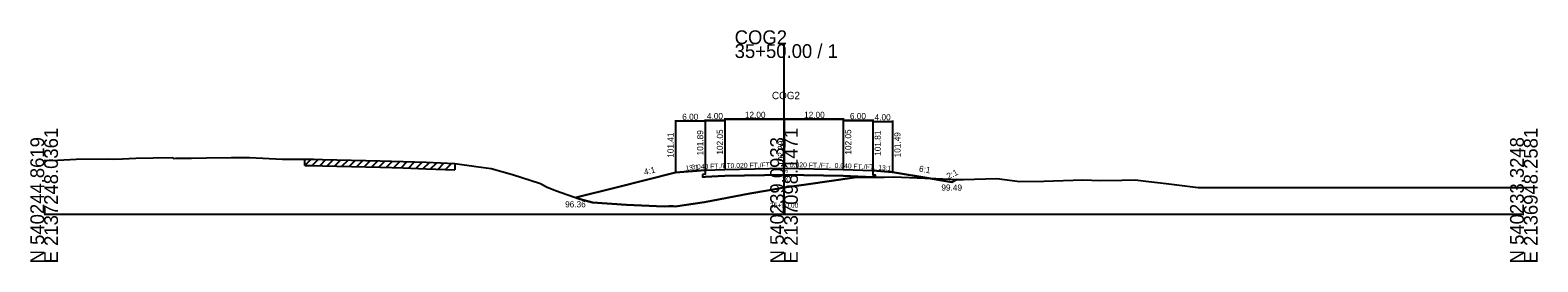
# Model space of a CAD drawing. Extents: x -13397 to 2303, y -10 to 39059.
# Drawn here: x 997.2 to 1302.8, y 10990.3 to 11037.3 of the extents above; entities that cross this region are included whole.
import ezdxf

# ---------------------------------------------------------------- set-up
doc = ezdxf.new("R2010")
doc.units = 0
for name, color, linetype in [('Level 5', 7, 'Continuous'), ('Level 53', 7, 'Continuous'), ('Level 54', 7, 'Continuous'), ('Level 55', 7, 'Continuous'), ('Level 7', 7, 'Continuous'), ('RD_GPK_XS_Cell', 7, 'Continuous'), ('RD_XS_EwShp', 7, 'Continuous'), ('RD_XS_ExGround', 7, 'Continuous'), ('RD_XS_ExPaveRet', 7, 'Continuous'), ('RD_XS_Pave', 7, 'Continuous'), ('RD_XS_TX_Baseline', 7, 'Continuous'), ('RD_XS_TX_Elev_EX', 7, 'Continuous'), ('RD_XS_TX_Elev_PR', 7, 'Continuous'), ('RD_XS_TX_Station', 7, 'Continuous')]:
    doc.layers.add(name, color=color, linetype=linetype)

msp = doc.modelspace()

# ---------------------------------------------------------------- linework, layer by layer
at = {"layer": 'Level 5'}
for p, q in [((1134, 11008.06), (1133.5, 11008.04)), ((1133.5, 11008.04), (1133.5, 11007.54)), ((1134, 11008.89), (1134, 11008.06)), ((1138, 11007.72), (1134, 11007.56)), ((1138, 11007.72), (1134, 11007.56)), ((1138, 11007.72), (1134, 11007.56)), ((1134, 11007.56), (1138, 11007.72)), ((1150, 11007.96), (1138, 11007.72)), ((1150, 11007.96), (1138, 11007.72)), ((1150, 11007.96), (1138, 11007.72)), ((1138, 11007.72), (1150, 11007.96)), ((1138, 11007.72), (1150, 11007.96)), ((1162, 11007.72), (1150, 11007.96)), ((1162, 11007.72), (1150, 11007.96)), ((1150, 11007.96), (1162, 11007.72)), ((1150, 11007.96), (1162, 11007.72)), ((1150, 11007.96), (1162, 11007.72)), ((1168, 11007.48), (1162, 11007.72)), ((1162, 11007.72), (1168, 11007.48)), ((1162, 11007.72), (1168, 11007.48)), ((1162, 11007.72), (1168, 11007.48)), ((1168, 11008.81), (1168, 11007.98)), ((1168, 11007.98), (1168.5, 11007.96)), ((1168.5, 11007.96), (1168.5, 11007.46)), ((1133.5, 11007.54), (1134, 11007.56)), ((1168.5, 11007.46), (1168, 11007.48))]:
    msp.add_line(p, q, dxfattribs=at)
at = {"layer": 'Level 54'}
for p, q in [((1128, 11019.04), (1128, 11008.61)), ((1134, 11018.84), (1128, 11018.84)), ((1134, 11019.2), (1134, 11009.09)), ((1134, 11019.2), (1134, 11009.09)), ((1134, 11019.2), (1134, 11009.09)), ((1134, 11019.2), (1134, 11009.09)), ((1134, 11019.04), (1134, 11009.09)), ((1134, 11019), (1138, 11019)), ((1134, 11019), (1138, 11019)), ((1134, 11019), (1138, 11019)), ((1138, 11019), (1134, 11019)), ((1138, 11019.44), (1138, 11009.25)), ((1138, 11019.44), (1138, 11009.25)), ((1138, 11019.44), (1138, 11009.25)), ((1138, 11019.44), (1138, 11009.25)), ((1138, 11019.44), (1138, 11009.25)), ((1138, 11019.24), (1150, 11019.24)), ((1138, 11019.24), (1150, 11019.24)), ((1138, 11019.24), (1150, 11019.24)), ((1150, 11019.24), (1138, 11019.24)), ((1150, 11019.24), (1138, 11019.24)), ((1138, 11019.2), (1138, 11009.25)), ((1138, 11019.2), (1138, 11009.25)), ((1138, 11019.2), (1138, 11009.25)), ((1138, 11019.2), (1138, 11009.25)), ((1150, 11019.44), (1150, 11009.49)), ((1150, 11019.44), (1150, 11009.49)), ((1150, 11019.44), (1150, 11009.49)), ((1150, 11019.44), (1150, 11009.49)), ((1150, 11019.44), (1150, 11009.49)), ((1150, 11019.44), (1150, 11009.49)), ((1150, 11019.44), (1150, 11009.49)), ((1150, 11019.44), (1150, 11009.49)), ((1150, 11019.44), (1150, 11009.49)), ((1150, 11019.44), (1150, 11009.49)), ((1150, 11019.24), (1162, 11019.24)), ((1150, 11019.24), (1162, 11019.24)), ((1162, 11019.24), (1150, 11019.24)), ((1162, 11019.24), (1150, 11019.24)), ((1162, 11019.24), (1150, 11019.24)), ((1162, 11019.44), (1162, 11009.25)), ((1162, 11019.44), (1162, 11009.25)), ((1162, 11019.44), (1162, 11009.25)), ((1162, 11019.44), (1162, 11009.25)), ((1162, 11019.44), (1162, 11009.25)), ((1162, 11019.2), (1162, 11009.25)), ((1162, 11019.2), (1162, 11009.25)), ((1162, 11019.2), (1162, 11009.25)), ((1162, 11019.2), (1162, 11009.25)), ((1162, 11019), (1168, 11019)), ((1168, 11019), (1162, 11019)), ((1168, 11019), (1162, 11019)), ((1168, 11019), (1162, 11019)), ((1168, 11019.2), (1168, 11009.01)), ((1168, 11019.2), (1168, 11009.01)), ((1168, 11019.2), (1168, 11009.01)), ((1168, 11019.2), (1168, 11009.01)), ((1168, 11018.96), (1168, 11009.01)), ((1168, 11018.76), (1172, 11018.76)), ((1172, 11018.96), (1172, 11008.69))]:
    msp.add_line(p, q, dxfattribs=at)
at = {"layer": 'Level 7'}
for p, q in [((1128, 11008.41), (1116, 11005.41)), ((1134, 11008.89), (1128, 11008.41)), ((1168, 11008.81), (1172, 11008.49)), ((1172, 11008.49), (1184, 11006.49)), ((1116, 11005.41), (1107.78, 11003.36)), ((1184, 11006.49), (1185.06, 11007.02))]:
    msp.add_line(p, q, dxfattribs=at)
at = {"layer": 'RD_GPK_XS_Cell'}
for p, q in [((1150, 11000), (1150, 11034.45)), ((1000, 11000), (1150, 11000)), ((1150, 11000), (1300, 11000))]:
    msp.add_line(p, q, dxfattribs=at)
at = {"layer": 'RD_XS_EwShp'}
for points in [[(1133.5, 11008.04), (1133.5, 11007.54), (1134, 11007.56), (1138, 11007.72), (1150, 11007.96), (1162, 11007.72), (1168, 11007.48), (1168.5, 11007.46), (1164.28, 11007.38), (1154.5, 11006), (1150.06, 11005.36), (1146.68, 11004.81), (1143.08, 11004.16), (1138.46, 11003.29), (1133.9, 11002.39), (1127.96, 11001.5), (1127.53, 11001.6), (1126.64, 11001.58), (1125.71, 11001.5), (1118.09, 11001.87), (1111.16, 11002.31), (1108.69, 11003.04), (1107.78, 11003.36), (1116, 11005.41), (1128, 11008.41), (1134, 11008.89), (1134, 11008.06)], [(1168, 11008.81), (1168, 11007.98), (1168.5, 11007.96), (1168.5, 11007.46), (1170.31, 11007.49), (1172.25, 11007.54), (1178.57, 11007.3), (1179.33, 11007.27), (1172, 11008.49)], [(1179.33, 11007.27), (1185.03, 11007.02), (1185.06, 11007.02), (1184, 11006.49)]]:
    msp.add_lwpolyline(points, close=True, dxfattribs=at)
at = {"layer": 'RD_XS_ExGround'}
for p, q in [((1000, 11010.87), (1002.79, 11010.96)), ((1002.79, 11010.96), (1006.48, 11011.1)), ((1006.48, 11011.1), (1013.02, 11011.22)), ((1013.02, 11011.22), (1014.14, 11011.11)), ((1014.14, 11011.11), (1015.89, 11011.19)), ((1015.89, 11011.19), (1018.61, 11011.33)), ((1018.61, 11011.33), (1022.08, 11011.41)), ((1022.08, 11011.41), (1026.07, 11011.45)), ((1026.07, 11011.45), (1026.14, 11011.27)), ((1026.14, 11011.27), (1026.65, 11011.36)), ((1026.65, 11011.36), (1029.87, 11011.36)), ((1029.87, 11011.36), (1032.92, 11011.42)), ((1032.92, 11011.42), (1037.94, 11011.48)), ((1037.94, 11011.48), (1041.62, 11011.44)), ((1041.62, 11011.44), (1048.32, 11011.16)), ((1048.32, 11011.16), (1052.86, 11011.15)), ((1052.86, 11011.15), (1054.66, 11011.12)), ((1054.66, 11011.12), (1056.45, 11011.09)), ((1056.45, 11011.09), (1068.09, 11010.79)), ((1068.09, 11010.79), (1072.78, 11010.66)), ((1072.78, 11010.66), (1077.47, 11010.49)), ((1077.47, 11010.49), (1083.23, 11010.28)), ((1083.23, 11010.28), (1087.56, 11009.67)), ((1087.56, 11009.67), (1090.66, 11009.22)), ((1090.66, 11009.22), (1094.93, 11007.99)), ((1094.93, 11007.99), (1100.61, 11006.21)), ((1100.61, 11006.21), (1101.88, 11005.52)), ((1101.88, 11005.52), (1103.66, 11004.8)), ((1103.66, 11004.8), (1108.69, 11003.04)), ((1143.08, 11004.16), (1146.68, 11004.81)), ((1146.68, 11004.81), (1150.06, 11005.36)), ((1150.06, 11005.36), (1154.5, 11006)), ((1154.5, 11006), (1164.28, 11007.38)), ((1164.28, 11007.38), (1170.31, 11007.49)), ((1170.31, 11007.49), (1172.25, 11007.54)), ((1172.25, 11007.54), (1178.57, 11007.3)), ((1178.57, 11007.3), (1185.03, 11007.02)), ((1185.03, 11007.02), (1185.61, 11007.04)), ((1185.61, 11007.04), (1186.42, 11007)), ((1186.42, 11007), (1193.16, 11007.19)), ((1193.16, 11007.19), (1197.82, 11006.57)), ((1197.82, 11006.57), (1202.7, 11006.68)), ((1202.7, 11006.68), (1210.6, 11006.92)), ((1210.6, 11006.92), (1214.2, 11006.78)), ((1214.2, 11006.78), (1218.52, 11006.9)), ((1218.52, 11006.9), (1221.22, 11006.96)), ((1221.22, 11006.96), (1223.38, 11006.64)), ((1223.38, 11006.64), (1227.46, 11006.19)), ((1227.46, 11006.19), (1233.96, 11005.39)), ((1233.96, 11005.39), (1235.55, 11005.39)), ((1235.55, 11005.39), (1237.69, 11005.39)), ((1237.69, 11005.39), (1253.88, 11005.39)), ((1253.88, 11005.39), (1256.69, 11005.39)), ((1256.69, 11005.39), (1268.04, 11005.39)), ((1268.04, 11005.39), (1276.5, 11005.39)), ((1276.5, 11005.39), (1282.56, 11005.39)), ((1282.56, 11005.39), (1289.35, 11005.39)), ((1289.35, 11005.39), (1293.49, 11005.39)), ((1293.49, 11005.39), (1296.93, 11005.39)), ((1296.93, 11005.39), (1300, 11005.39)), ((1108.69, 11003.04), (1111.16, 11002.31)), ((1111.16, 11002.31), (1118.09, 11001.87)), ((1118.09, 11001.87), (1125.71, 11001.5)), ((1125.71, 11001.5), (1126.64, 11001.58)), ((1126.64, 11001.58), (1127.53, 11001.6)), ((1127.53, 11001.6), (1127.96, 11001.5)), ((1127.96, 11001.5), (1133.9, 11002.39)), ((1133.9, 11002.39), (1138.46, 11003.29)), ((1138.46, 11003.29), (1143.08, 11004.16))]:
    msp.add_line(p, q, dxfattribs=at)
at = {"layer": 'RD_XS_ExPaveRet'}
for p, q in [((1052.86, 11009.85), (1052.86, 11011.15)), ((1052.86, 11009.85), (1054.14, 11011.13)), ((1054.36, 11009.83), (1055.64, 11011.11)), ((1055.86, 11009.8), (1057.13, 11011.07)), ((1057.36, 11009.77), (1058.63, 11011.04)), ((1058.86, 11009.73), (1060.13, 11011)), ((1060.36, 11009.69), (1061.63, 11010.96)), ((1061.86, 11009.65), (1063.13, 11010.92)), ((1063.36, 11009.61), (1064.63, 11010.88)), ((1064.86, 11009.57), (1066.13, 11010.84)), ((1066.36, 11009.53), (1067.63, 11010.8)), ((1067.86, 11009.49), (1069.13, 11010.76)), ((1069.36, 11009.45), (1070.63, 11010.72)), ((1070.86, 11009.41), (1072.13, 11010.68)), ((1052.86, 11009.85), (1054.66, 11009.82)), ((1054.66, 11009.82), (1056.45, 11009.79)), ((1056.45, 11009.79), (1068.09, 11009.49)), ((1068.09, 11009.49), (1072.78, 11009.36)), ((1072.36, 11009.37), (1073.62, 11010.63)), ((1072.78, 11009.36), (1077.47, 11009.19)), ((1073.86, 11009.32), (1075.11, 11010.57)), ((1075.36, 11009.27), (1076.62, 11010.52)), ((1076.86, 11009.21), (1078.12, 11010.47)), ((1077.47, 11009.19), (1083.23, 11008.98)), ((1078.36, 11009.16), (1079.62, 11010.41)), ((1079.86, 11009.1), (1081.12, 11010.36)), ((1081.36, 11009.05), (1082.62, 11010.3)), ((1083.23, 11010.28), (1083.23, 11008.98))]:
    msp.add_line(p, q, dxfattribs=at)
at = {"layer": 'RD_XS_Pave'}
for p, q in [((1134, 11008.89), (1138, 11009.05)), ((1138, 11009.05), (1150, 11009.29)), ((1150, 11009.29), (1162, 11009.05)), ((1162, 11009.05), (1168, 11008.81))]:
    msp.add_line(p, q, dxfattribs=at)

# ---------------------------------------------------------------- texts
at = {"layer": 'Level 53'}
for s, rotation, p in [('101.89', 90, (1133.62, 11011.89)), ('102.05', 90, (1137.63, 11012.05)), ('102.05', 90, (1137.63, 11012.05)), ('102.05', 90, (1137.63, 11012.05)), ('102.05', 90, (1163.63, 11012.05)), ('102.05', 90, (1163.63, 11012.05)), ('102.05', 90, (1163.63, 11012.05)), ('101.81', 90, (1169.62, 11011.81)), ('101.41', 90, (1127.62, 11011.41)), ('101.49', 90, (1173.62, 11011.49)), ('4:1', 14.0362, (1121.76, 11007.88)), ('6:1', 350.5377, (1177.3, 11008.62))]:
    msp.add_text(s, height=1.25, rotation=rotation, dxfattribs=at).set_placement(p)
for s, p in [('99.49', (1181.91, 11004.74)), ('96.36', (1105.62, 11001.36))]:
    msp.add_text(s, height=1.25, dxfattribs=at).set_placement(p)
at = {"layer": 'Level 54'}
for s, p in [('6.00', (1129.37, 11019.09)), ('4.00', (1134.37, 11019.25)), ('4.00', (1134.37, 11019.25)), ('4.00', (1134.37, 11019.25)), ('4.00', (1134.37, 11019.25)), ('12.00', (1142.07, 11019.49)), ('12.00', (1142.07, 11019.49)), ('12.00', (1142.07, 11019.49)), ('12.00', (1142.07, 11019.49)), ('12.00', (1142.07, 11019.49)), ('12.00', (1154.07, 11019.49)), ('12.00', (1154.07, 11019.49)), ('12.00', (1154.07, 11019.49)), ('12.00', (1154.07, 11019.49)), ('12.00', (1154.07, 11019.49)), ('6.00', (1163.37, 11019.25)), ('6.00', (1163.37, 11019.25)), ('6.00', (1163.37, 11019.25)), ('6.00', (1163.37, 11019.25)), ('4.00', (1168.37, 11019.01))]:
    msp.add_text(s, height=1.25, dxfattribs=at).set_placement(p)
at = {"layer": 'Level 55'}
for s, height, rotation, p in [('13:1', 1, 4.5739, (1130.03, 11008.82)), ('0.040 FT./FT.', 1, 2.2906, (1131.22, 11009.03)), ('0.040 FT./FT.', 1, 2.2906, (1131.22, 11009.03)), ('0.040 FT./FT.', 1, 2.2906, (1131.22, 11009.03)), ('0.040 FT./FT.', 1, 2.2906, (1131.22, 11009.03)), ('0.020 FT./FT.', 1, 1.1458, (1139.17, 11009.32)), ('0.020 FT./FT.', 1, 1.1458, (1139.17, 11009.32)), ('0.020 FT./FT.', 1, 1.1458, (1139.17, 11009.32)), ('0.020 FT./FT.', 1, 1.1458, (1139.17, 11009.32)), ('0.020 FT./FT.', 1, 1.1458, (1139.17, 11009.32)), ('0.020 FT./FT.', 1, 358.8542, (1151.18, 11009.52)), ('0.020 FT./FT.', 1, 358.8542, (1151.18, 11009.52)), ('0.020 FT./FT.', 1, 358.8542, (1151.18, 11009.52)), ('0.020 FT./FT.', 1, 358.8542, (1151.18, 11009.52)), ('0.020 FT./FT.', 1, 358.8542, (1151.18, 11009.52)), ('0.040 FT./FT.', 1, 357.7094, (1160.24, 11009.37)), ('0.040 FT./FT.', 1, 357.7094, (1160.24, 11009.37)), ('0.040 FT./FT.', 1, 357.7094, (1160.24, 11009.37)), ('0.040 FT./FT.', 1, 357.7094, (1160.24, 11009.37)), ('13:1', 1, 355.4261, (1169.07, 11008.98)), ('2:1', 1.25, 26.5651, (1183.35, 11007.01))]:
    msp.add_text(s, height=height, rotation=rotation, dxfattribs=at).set_placement(p)
at = {"layer": 'RD_GPK_XS_Cell'}
for s, p in [('COG2', (1140, 11034.45)), ('35+50.00 / 1', (1140, 11031.65))]:
    msp.add_text(s, height=2.8, dxfattribs=at).set_placement(p)
for s, p in [('E 2137248.0361', (1002.8, 10990)), ('E 2137098.1471', (1152.8, 10990)), ('E 2136948.2581', (1302.8, 10990)), ('N 540244.8619', (1000, 10990)), ('N 540239.0933', (1150, 10990)), ('N 540233.3248', (1300, 10990))]:
    msp.add_text(s, height=2.8, rotation=90, dxfattribs=at).set_placement(p)
at = {"layer": 'RD_XS_TX_Baseline'}
msp.add_text('COG2', height=1.5, dxfattribs=at).set_placement((1147.55, 11023.29))
at = {"layer": 'RD_XS_TX_Elev_EX'}
msp.add_text('98.35', height=1, rotation=90, dxfattribs=at).set_placement((1150.75, 11006.35))
at = {"layer": 'RD_XS_TX_Elev_PR'}
msp.add_text(' 102.29', height=1.25, rotation=90, dxfattribs=at).set_placement((1150, 11009.29))
at = {"layer": 'RD_XS_TX_Station'}
msp.add_text('35+50.00', height=1, dxfattribs=at).set_placement((1147.12, 11001.29))

doc.saveas('drawing.dxf')
